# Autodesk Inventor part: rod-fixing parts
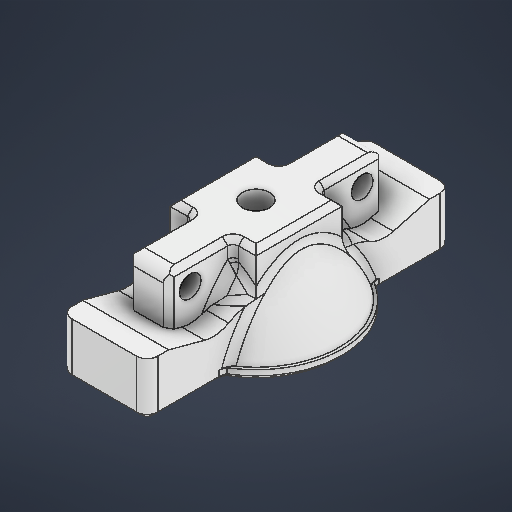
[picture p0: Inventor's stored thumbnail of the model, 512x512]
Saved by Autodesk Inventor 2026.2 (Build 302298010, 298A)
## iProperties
Created: 2026-05
Part Number: rod-fixing parts
Material: ABS 플라스틱
Document SubType Name: Modeling
Designer: work
Density: 1.06 g/cm^3
Appearance: 매끄러움 - 흰색
Author: work
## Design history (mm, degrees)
sketch "스케치1"
  geometry: L1 (-8, 8)-(8, 8); L2 (8, 8)-(8, -8); L3 (8, -8)-(-8, -8); L4 (-8, -8)-(-8, 8); L5 (-8, 8)-(8, -8); L6 (8, 8)-(-8, -8); L7 (-3.75, 20)-(3.75, 20); L8 (3.75, 20)-(3.75, -20); L9 (3.75, -20)-(-3.75, -20); L10 (-3.75, -20)-(-3.75, 20); L11 (-3.75, 20)-(3.75, -20); L12 (3.75, 20)-(-3.75, -20); C1 r 2.5 at (0, 0); 5 further points
  constraints: 24 end point, 4 midpoint, 4 parallel, 2 horizontal, 2 perpendicular, 1 centre point, 1 coincident
  dimensions: "d0" = 16 distance of L2.end L3.end; "d1" = 16 distance of L1.end L2.end; "d2" = 5 diameter of C1; "d3" = 12 distance between parallel lines of L9 L3; "d4" = 7.5 distance of L8.end L9.end
extrude "돌출1" new body sketch "스케치1" distance "d5" = 8; taper "d6" = 0 deg
sketch "스케치2"
  geometry: L1 (0, 0)-(12, 0) reference; L2 (12, 0)-(12, 8) reference; L3 (0, 8)-(12, 8) reference; L4 (0, 0)-(0, 8) reference; L5 (28, 0)-(40, 0) reference; L6 (40, 0)-(40, 8) reference; L7 (28, 8)-(40, 8) reference; L8 (28, 0)-(28, 8) reference; L9 (40, 0)-(40, 8) reference; L10 (40, 4)-(28, 4); L11 (12, 4)-(0, 4); C1 r 2 at (4, 4); C2 r 2 at (36, 4); 1 further point
  constraints: 4 end point, 4 midpoint, 2 centre point, 2 point on line
  dimensions: "d7" = 4 diameter of C2; "d8" = 4 distance from line of L6 C2.centre; "d9" = 4 distance from line of L4 C1.centre; "d10" = 4 diameter of C1
extrude "돌출2" cut sketch "스케치2" extent not by distance; stored distance "d11" = 0; taper "d12" = 0 deg
fillet "모깎기2" dims "d14" = 1
sketch "스케치4"
  geometry: L1 (-1, 8)-(-1, 0) reference; L2 (-12, 8)-(-1, 8) reference; L3 (-12, 0)-(-12, 8) reference; L4 (-12, 0)-(-1, 0) reference; L5 (17, 0)-(17, 8) reference; L6 (17, 0)-(28, 0) reference; L7 (28, 0)-(28, 8) reference; L8 (17, 8)-(28, 8) reference; L9 (5.5, 8)-(10.5, 8) reference; L10 (8, 8)-(8, -6.499); L11 (8, -6.499)-(25.553, -1.796); L12 (25.553, -1.796)-(32.254, 0); L13 (8, 0)-(32.254, 0); L14 (32.254, 0)-(36.254, 0); L15 (36.254, 0)-(36.254, -10); L16 (24, 4)-(24, -10); L17 (24, -10)-(36.254, -10); L18 (0, 0)-(16, 0) reference; L19 (-8, 4)-(-8, -10); L20 (-1, 0)-(-12, 0); L21 (-12, 0)-(-12, 8); L22 (-1, 8)-(-12, 8); L23 (8, 0)-(-16.254, 0); L24 (8, -6.499)-(-9.553, -1.796); L25 (-1, 0)-(-1, 8); L26 (16, 0)-(0, 0); L27 (-16.254, 0)-(-20.254, 0); L28 (-8, -10)-(-20.254, -10); L29 (-20.254, 0)-(-20.254, -10); L30 (-9.553, -1.796)-(-16.254, 0); C1 r 2 at (-8, 4) reference; C2 r 2 at (24, 4) reference; C3 r 6 at (-8, 4); C4 r 2 at (-8, 4); A1 r 6 centre (24, 4) between (25.553, -1.796) and (21.095, -1.25); A2 r 40 centre (7.631, -46.497) between (24, -10) and (8, -6.499); A3 r 10 centre (16.254, -10) between (21.095, -1.25) and (16.254, 0); A4 r 10 centre (-0.254, -10) between (-0.254, 0) and (-5.095, -1.25); A5 r 6 centre (-8, 4) between (-9.553, -1.796) and (-5.095, -1.25); A6 r 40 centre (8.369, -46.497) between (8, -6.499) and (-8, -10); 7 further points
  constraints: 40 end point, 13 symmetric about line, 12 point on circle, 8 centre point, 4 point on line, 3 coincident, 3 perpendicular, 3 tangent, 1 collinear, 1 horizontal, 1 midpoint, 1 vertical, 4 other
  dimensions: "d21" = 12 diameter of C3; "d22" = 12 diameter of A1; "d23" = 75 deg angle of L10 L11; "d24" = 40 radius of A2; "d25" = 4 distance of L12.end L14.end; "d26" = 10 distance between parallel lines of L14 L17; "d27" = 10 radius of A3
extrude "돌출3" join sketch "스케치4" stored distance "d28" = 10; taper "d29" = 0 deg
sketch "스케치5"
  geometry: L1 (-8, 8)-(-4.75, 8) reference; L2 (-3.75, 9)-(-3.75, 20) reference; L3 (-3.75, 20)-(3.75, 20) reference; L4 (3.75, 20)-(3.75, 9) reference; L5 (4.75, 8)-(8, 8) reference; L6 (8, 8)-(8, -8) reference; L7 (8, -8)-(4.75, -8) reference; L8 (3.75, -9)-(3.75, -20) reference; L9 (3.75, -20)-(-3.75, -20) reference; L10 (-3.75, -20)-(-3.75, -9) reference; L11 (-4.75, -8)-(-8, -8) reference; L12 (-8, -8)-(-8, 8) reference; C1 r 2.5 at (0, 0) reference; A1 r 1 centre (-4.75, 9) between (-4.75, 8) and (-3.75, 9) reference; A2 r 1 centre (4.75, 9) between (3.75, 9) and (4.75, 8) reference; A3 r 1 centre (4.75, -9) between (4.75, -8) and (3.75, -9) reference; A4 r 1 centre (-4.75, -9) between (-3.75, -9) and (-4.75, -8) reference; 1 further point
extrude "돌출4" join sketch "스케치5" distance "d30" = 5; taper "d31" = 0 deg
sketch "스케치6"
  geometry: C1 r 6 at (-8, 28.254); 1 further point
  constraints: 1 centre point, 1 coincident
  dimensions: "d32" = 12 diameter of C1
extrude "돌출5" cut sketch "스케치6" distance "d33" = 12; taper "d34" = 0 deg
sketch "스케치7"
  geometry: L1 (8, 2.5)-(8, -2.5) reference; L2 (8, 0)-(-12.782, 0); L3 (-12.782, 0)-(-10, 16); L4 (2, -6)-(2, 6) reference; L5 (2, 6)-(8, 6); L6 (8, 9)-(-0.028, 9) reference; A1 r 40 centre (-46.497, -0.369) between (-6.499, 0) and (-10, 16) reference; A2 r 30 centre (-17.854, -16.491) between (2, 6) and (-8.458, 12); A3 r 32.562 centre (-17.854, -16.491) between (10.722, -0.878) and (-9.568, 15); 2 further points
  constraints: 6 end point, 6 point on circle, 2 centre point, 1 concentric, 1 horizontal, 1 midpoint, 1 parallel
  dimensions: "d35" = 30 radius of A2; "d36" = 12 distance from line of L2 A2.end; "d38" = 3 vertical distance of A2.end A3.end
revolve "회전1" sketch "스케치7" stored, may be unused: angle "d37" = 360 deg
chamfer "모따기3" distance "d41" = 1; stored, may be unused: second distance "d42" = 2, angle "d43" = 45 deg
sketch "스케치8"
  geometry: L1 (7, 8)-(7, -8) reference; L2 (0, 8)-(7, 8) reference; L3 (0, 8)-(0, 8.254) reference; L4 (-1.796, 17.553)-(0, 24.254) reference; L5 (0, 24.254)-(0, 28.254) reference; L6 (0, 28.254)-(-10, 28.254) reference; L7 (-10, 28.254)-(-10, 16) reference; L8 (-10, -16)-(-10, -28.254) reference; L9 (-10, -28.254)-(0, -28.254) reference; L10 (0, -28.254)-(0, -24.254) reference; L11 (0, -24.254)-(-1.796, -17.553) reference; L12 (0, -8.254)-(0, -8) reference; L13 (0, -8)-(7, -8) reference; L14 (7, 0)-(-0.527, 0); L15 (8, -7)-(8, 7) reference; L16 (2, -6)-(2, 6) reference; L17 (8, -2.5)-(2, -2.5) reference; A1 r 30 centre (-17.854, 16.491) between (-8.458, -12) and (2, -6) reference; A2 r 40 centre (-46.497, 0.369) between (-10, -16) and (-7.49, -8.486) reference; A3 r 10 centre (-10, 8.254) between (0, 8.254) and (-1.25, 13.095) reference; A4 r 6 centre (4, 16) between (-1.796, 17.553) and (-1.25, 13.095) reference; A5 r 40 centre (-46.497, -0.369) between (-7.49, 8.486) and (-10, 16) reference; A6 r 40 centre (-46.497, 0.369) between (-10, -16) and (-7.49, -8.486) reference; A7 r 6 centre (4, -16) between (-1.25, -13.095) and (-1.796, -17.553) reference; A8 r 10 centre (-10, -8.254) between (-1.25, -13.095) and (0, -8.254) reference; A9 r 33.426 centre (-17.854, 16.491) between (-10, -16) and (-0.849, -12.287); 6 further points
  constraints: 3 point on circle, 2 end point, 1 centre point, 1 coincident, 1 concentric, 1 midpoint, 1 perpendicular, 5 other
revolve "회전2" sketch "스케치8" stored, may be unused: angle "d44" = 90 deg
fillet "모깎기5" dims "d45" = 2
sketch "스케치9"
  geometry: L1 (0, 9.831)-(0, 0) reference; L2 (-16, 9.831)-(0, 9.831) reference; L3 (-16, 9.831)-(-16, 0) reference; L4 (-2, -2)-(-14, -2) reference; L5 (0, 50.508)-(-16, 50.508) reference; L6 (-2, 54.508)-(-14, 54.508) reference; L7 (-16, 52.508)-(-16, 42.677) reference; L8 (0, 42.677)-(-16, 42.677) reference; L9 (0, 52.508)-(0, 42.677) reference; L10 (-16, 9.831)-(0, 9.831); L11 (0, 9.831)-(0, 42.677); L12 (0, 42.677)-(-16, 42.677); L13 (-16, 42.677)-(-16, 9.831); C1 r 12.904 at (-8, 26.254) reference; C2 r 16 at (-8, 26.254) reference; A1 r 2 centre (-2, 0) between (-2, -2) and (0, 0) reference; A2 r 2 centre (-14, 0) between (-16, 0) and (-14, -2) reference; A3 r 2 centre (-2, 52.508) between (0, 52.508) and (-2, 54.508) reference; A4 r 2 centre (-14, 52.508) between (-14, 54.508) and (-16, 52.508) reference; 15 further points
  constraints: 8 end point, 2 parallel, 1 horizontal, 1 perpendicular, 4 other
extrude "돌출6" join sketch "스케치9" distance "d46" = 2; taper "d47" = 0 deg
sketch "스케치10"
  geometry: C1 r 14 at (6, 28.254); A1 r 16 centre (6, 28.254) between (14.275, 41.948) and (-2.275, 41.948) reference; A2 r 16 centre (6, 28.254) between (-2.275, 41.948) and (-2.275, 14.56) reference; 4 further points
  constraints: 2 coincident, 1 centre point, 3 other
  dimensions: "d48" = 2 radial gap between concentric circles of A1 C1
extrude "돌출7" join sketch "스케치10" distance "d49" = 2; taper "d50" = 0 deg
chamfer "모따기4" distance "d51" = 1; stored, may be unused: second distance "d52" = 2, angle "d53" = 45 deg
node "솔리드1"
node "투영된 루프1"
node "투영된 루프2"
node "투영된 루프5"
node "투영된 루프6"
node "투영된 루프7"
node "투영된 루프8"
node "투영된 루프9"
node "투영된 루프10"
